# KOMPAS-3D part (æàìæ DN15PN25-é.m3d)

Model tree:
1. Объединить компоненты:1  (labels: СЕНС DN15PN25-В)

Referenced files in D:\Савин\!СЕНСОР\3D для заказчика\!Новый перечень\СЕНС\3. СЕНС-В\DN15\: СЕНС DN15PN25-В.a3d
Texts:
  СЕНС DN15PN25-В
  ООО НПП Сенсор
